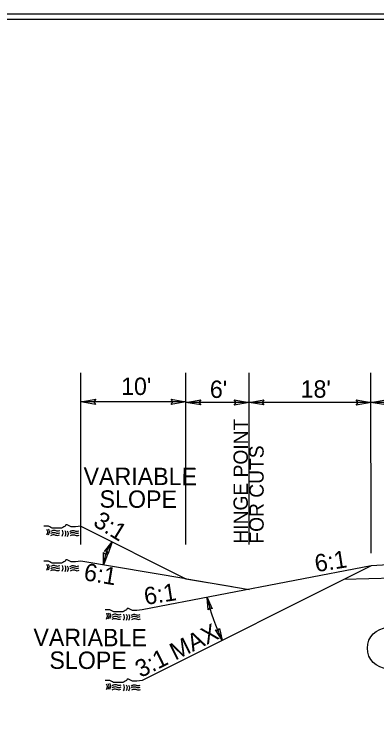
# Model space of a CAD drawing. Extents: x 2241081 to 2251104, y 658534 to 663427.
# Drawn here: x 2247921.2 to 2248093.7, y 660369.2 to 660704.3 of the extents above; entities that cross this region are included whole.
import ezdxf

# ---------------------------------------------------------------- set-up
doc = ezdxf.new("R2010")
doc.units = 0
for name, color, linetype in [('Old_Level_1', 7, 'Continuous'), ('Old_Level_2', 7, 'Continuous'), ('Prop Dimension', 7, 'Continuous'), ('Prop Dimension Text', 7, 'Continuous'), ('Prop PHM Text', 7, 'Continuous'), ('Sheet Plan CELL', 7, 'Continuous'), ('Sheet Plot Border Inside CELL', 7, 'Continuous'), ('Typical Hinge Slope Interstate CELL', 7, 'Continuous'), ('Typical ID Circle CELL', 7, 'Continuous'), ('Typical Terminator CELL', 7, 'Continuous')]:
    doc.layers.add(name, color=color, linetype=linetype)

msp = doc.modelspace()

# ---------------------------------------------------------------- linework, layer by layer
at = {"layer": 'Old_Level_1'}
for p, q in [((2247952.96, 660461.2), (2248002.96, 660436.2)), ((2248002.96, 660436.2), (2247952.96, 660444.54)), ((2248090.97, 660442.37), (2247982.14, 660421.42)), ((2248002.96, 660436.2), (2248024.96, 660432.54))]:
    msp.add_line(p, q, dxfattribs=at)
for points in [[(2247952.96, 660461.2), (2247950.49, 660460.9), (2247949.88, 660460.9), (2247948.95, 660460.9), (2247948.34, 660460.9), (2247947.72, 660461.2), (2247947.1, 660461.51), (2247946.49, 660461.82), (2247945.87, 660461.82), (2247945.56, 660461.2), (2247944.95, 660460.9), (2247944.33, 660460.59), (2247943.71, 660460.28), (2247943.1, 660460.28), (2247942.48, 660460.28), (2247941.87, 660460.28), (2247941.25, 660460.28), (2247940.63, 660460.28), (2247940.02, 660460.28), (2247939.4, 660460.28), (2247938.78, 660460.59), (2247938.17, 660460.9), (2247937.55, 660461.2), (2247936.63, 660461.2), (2247936.01, 660461.2), (2247935.39, 660461.2)], [(2247952.96, 660444.54), (2247950.49, 660444.23), (2247949.88, 660444.23), (2247948.95, 660444.23), (2247948.34, 660444.23), (2247947.72, 660444.54), (2247947.1, 660444.85), (2247946.49, 660445.16), (2247945.87, 660445.16), (2247945.56, 660444.54), (2247944.95, 660444.23), (2247944.33, 660443.92), (2247943.71, 660443.62), (2247943.1, 660443.62), (2247942.48, 660443.62), (2247941.87, 660443.62), (2247941.25, 660443.62), (2247940.63, 660443.62), (2247940.02, 660443.62), (2247939.4, 660443.62), (2247938.78, 660443.92), (2247938.17, 660444.23), (2247937.55, 660444.54), (2247936.63, 660444.54), (2247936.01, 660444.54), (2247935.39, 660444.54)], [(2247982.14, 660421.42), (2247979.67, 660421.12), (2247979.06, 660421.12), (2247978.13, 660421.12), (2247977.51, 660421.12), (2247976.9, 660421.42), (2247976.28, 660421.73), (2247975.67, 660422.04), (2247975.05, 660422.04), (2247974.74, 660421.42), (2247974.12, 660421.12), (2247973.51, 660420.81), (2247972.89, 660420.5), (2247972.28, 660420.5), (2247971.66, 660420.5), (2247971.04, 660420.5), (2247970.43, 660420.5), (2247969.81, 660420.5), (2247969.2, 660420.5), (2247968.58, 660420.5), (2247967.96, 660420.81), (2247967.35, 660421.12), (2247966.73, 660421.42), (2247965.81, 660421.42), (2247965.19, 660421.42), (2247964.57, 660421.42)], [(2247982.13, 660387.95), (2247979.67, 660387.64), (2247979.05, 660387.64), (2247978.12, 660387.64), (2247977.51, 660387.64), (2247976.89, 660387.95), (2247976.28, 660388.26), (2247975.66, 660388.57), (2247975.04, 660388.57), (2247974.73, 660387.95), (2247974.12, 660387.64), (2247973.5, 660387.33), (2247972.89, 660387.03), (2247972.27, 660387.03), (2247971.65, 660387.03), (2247971.04, 660387.03), (2247970.42, 660387.03), (2247969.81, 660387.03), (2247969.19, 660387.03), (2247968.57, 660387.03), (2247967.96, 660387.33), (2247967.34, 660387.64), (2247966.72, 660387.95), (2247965.8, 660387.95), (2247965.18, 660387.95), (2247964.57, 660387.95)]]:
    msp.add_lwpolyline(points, dxfattribs=at)
for points in [[(2247936.65, 660459.76), (2247937.07, 660458.51), (2247936.61, 660456.87)], [(2247936.65, 660459.76), (2247937.07, 660458.51), (2247936.61, 660456.87)], [(2247937.43, 660459.84), (2247937.85, 660458.6), (2247937.4, 660456.95)], [(2247937.43, 660459.84), (2247937.85, 660458.6), (2247937.4, 660456.95)], [(2247938.75, 660457.83), (2247940.26, 660458.25), (2247941.84, 660457.84), (2247942.98, 660458.1)], [(2247938.75, 660457.83), (2247940.26, 660458.25), (2247941.84, 660457.84), (2247942.98, 660458.1)], [(2247938.76, 660458.87), (2247940.26, 660459.3), (2247941.85, 660458.9), (2247942.99, 660459.16)], [(2247938.76, 660458.87), (2247940.26, 660459.3), (2247941.85, 660458.9), (2247942.99, 660459.16)], [(2247944.02, 660459.23), (2247944.43, 660457.99), (2247943.99, 660456.34)], [(2247944.02, 660459.23), (2247944.43, 660457.99), (2247943.99, 660456.34)], [(2247945.33, 660459.13), (2247945.75, 660457.88), (2247945.3, 660456.23)], [(2247945.33, 660459.13), (2247945.75, 660457.88), (2247945.3, 660456.23)], [(2247946.54, 660459.02), (2247946.96, 660457.77), (2247946.51, 660456.13)], [(2247946.54, 660459.02), (2247946.96, 660457.77), (2247946.51, 660456.13)], [(2247947.78, 660458.73), (2247949.29, 660459.16), (2247950.88, 660458.75), (2247952.03, 660459.01)], [(2247947.78, 660458.73), (2247949.29, 660459.16), (2247950.88, 660458.75), (2247952.03, 660459.01)], [(2247947.82, 660457.79), (2247949.33, 660458.22), (2247950.92, 660457.81), (2247952.06, 660458.07)], [(2247947.82, 660457.79), (2247949.33, 660458.22), (2247950.92, 660457.81), (2247952.06, 660458.07)], [(2247938.63, 660456.77), (2247940.14, 660457.19), (2247941.73, 660456.8), (2247942.88, 660457.05)], [(2247938.63, 660456.77), (2247940.14, 660457.19), (2247941.73, 660456.8), (2247942.88, 660457.05)], [(2247947.98, 660456.69), (2247949.48, 660457.12), (2247951.07, 660456.72), (2247952.22, 660456.98)], [(2247947.98, 660456.69), (2247949.48, 660457.12), (2247951.07, 660456.72), (2247952.22, 660456.98)], [(2247936.65, 660443.09), (2247937.07, 660441.85), (2247936.61, 660440.2)], [(2247936.65, 660443.09), (2247937.07, 660441.85), (2247936.61, 660440.2)], [(2247937.43, 660443.18), (2247937.85, 660441.93), (2247937.4, 660440.29)], [(2247937.43, 660443.18), (2247937.85, 660441.93), (2247937.4, 660440.29)], [(2247938.75, 660441.16), (2247940.26, 660441.59), (2247941.84, 660441.18), (2247942.98, 660441.44)], [(2247938.75, 660441.16), (2247940.26, 660441.59), (2247941.84, 660441.18), (2247942.98, 660441.44)], [(2247938.76, 660442.21), (2247940.26, 660442.64), (2247941.85, 660442.23), (2247942.99, 660442.49)], [(2247938.76, 660442.21), (2247940.26, 660442.64), (2247941.85, 660442.23), (2247942.99, 660442.49)], [(2247944.02, 660442.56), (2247944.43, 660441.32), (2247943.99, 660439.67)], [(2247944.02, 660442.56), (2247944.43, 660441.32), (2247943.99, 660439.67)], [(2247945.33, 660442.46), (2247945.75, 660441.22), (2247945.3, 660439.57)], [(2247945.33, 660442.46), (2247945.75, 660441.22), (2247945.3, 660439.57)], [(2247946.54, 660442.35), (2247946.96, 660441.11), (2247946.51, 660439.46)], [(2247946.54, 660442.35), (2247946.96, 660441.11), (2247946.51, 660439.46)], [(2247947.78, 660442.06), (2247949.29, 660442.49), (2247950.88, 660442.09), (2247952.03, 660442.34)], [(2247947.78, 660442.06), (2247949.29, 660442.49), (2247950.88, 660442.09), (2247952.03, 660442.34)], [(2247947.82, 660441.12), (2247949.33, 660441.55), (2247950.92, 660441.14), (2247952.06, 660441.4)], [(2247947.82, 660441.12), (2247949.33, 660441.55), (2247950.92, 660441.14), (2247952.06, 660441.4)], [(2247938.63, 660440.1), (2247940.14, 660440.53), (2247941.73, 660440.13), (2247942.88, 660440.39)], [(2247938.63, 660440.1), (2247940.14, 660440.53), (2247941.73, 660440.13), (2247942.88, 660440.39)], [(2247947.98, 660440.03), (2247949.48, 660440.46), (2247951.07, 660440.05), (2247952.22, 660440.31)], [(2247947.98, 660440.03), (2247949.48, 660440.46), (2247951.07, 660440.05), (2247952.22, 660440.31)]]:
    msp.add_spline(points, degree=3, dxfattribs=at)
at = {"layer": 'Old_Level_2'}
for p, q in [((2248140.97, 660445.12), (2248090.97, 660442.37)), ((2248300.97, 660440.7), (2248078.08, 660435.93))]:
    msp.add_line(p, q, dxfattribs=at)
for points in [[(2247965.1, 660419.83), (2247965.52, 660418.59), (2247965.06, 660416.95)], [(2247965.1, 660419.83), (2247965.52, 660418.59), (2247965.06, 660416.95)], [(2247965.83, 660419.98), (2247966.25, 660418.73), (2247965.79, 660417.08)], [(2247965.83, 660419.98), (2247966.25, 660418.73), (2247965.79, 660417.08)], [(2247966.61, 660420.06), (2247967.03, 660418.81), (2247966.58, 660417.17)], [(2247966.61, 660420.06), (2247967.03, 660418.81), (2247966.58, 660417.17)], [(2247967.81, 660416.99), (2247969.31, 660417.41), (2247970.91, 660417.02), (2247972.06, 660417.27)], [(2247967.81, 660416.99), (2247969.31, 660417.41), (2247970.91, 660417.02), (2247972.06, 660417.27)], [(2247967.93, 660418.04), (2247969.43, 660418.47), (2247971.02, 660418.06), (2247972.16, 660418.32)], [(2247967.93, 660418.04), (2247969.43, 660418.47), (2247971.02, 660418.06), (2247972.16, 660418.32)], [(2247967.94, 660419.09), (2247969.44, 660419.52), (2247971.03, 660419.12), (2247972.17, 660419.38)], [(2247967.94, 660419.09), (2247969.44, 660419.52), (2247971.03, 660419.12), (2247972.17, 660419.38)], [(2247973.19, 660419.44), (2247973.61, 660418.2), (2247973.17, 660416.56)], [(2247973.19, 660419.44), (2247973.61, 660418.2), (2247973.17, 660416.56)], [(2247974.51, 660419.34), (2247974.93, 660418.1), (2247974.48, 660416.45)], [(2247974.51, 660419.34), (2247974.93, 660418.1), (2247974.48, 660416.45)], [(2247975.72, 660419.23), (2247976.14, 660417.99), (2247975.69, 660416.35)], [(2247975.72, 660419.23), (2247976.14, 660417.99), (2247975.69, 660416.35)], [(2247976.96, 660418.95), (2247978.47, 660419.38), (2247980.05, 660418.97), (2247981.2, 660419.23)], [(2247976.96, 660418.95), (2247978.47, 660419.38), (2247980.05, 660418.97), (2247981.2, 660419.23)], [(2247977, 660418), (2247978.51, 660418.44), (2247980.09, 660418.03), (2247981.24, 660418.29)], [(2247977, 660418), (2247978.51, 660418.44), (2247980.09, 660418.03), (2247981.24, 660418.29)], [(2247977.16, 660416.91), (2247978.66, 660417.34), (2247980.25, 660416.94), (2247981.4, 660417.19)], [(2247965.09, 660386.36), (2247965.51, 660385.12), (2247965.06, 660383.47)], [(2247965.09, 660386.36), (2247965.51, 660385.12), (2247965.06, 660383.47)], [(2247965.82, 660386.5), (2247966.24, 660385.26), (2247965.78, 660383.61)], [(2247965.82, 660386.5), (2247966.24, 660385.26), (2247965.78, 660383.61)], [(2247966.6, 660386.59), (2247967.03, 660385.34), (2247966.57, 660383.7)], [(2247966.6, 660386.59), (2247967.03, 660385.34), (2247966.57, 660383.7)], [(2247967.8, 660383.51), (2247969.31, 660383.94), (2247970.9, 660383.54), (2247972.05, 660383.79)], [(2247967.8, 660383.51), (2247969.31, 660383.94), (2247970.9, 660383.54), (2247972.05, 660383.79)], [(2247967.92, 660384.57), (2247969.43, 660385), (2247971.01, 660384.59), (2247972.16, 660384.85)], [(2247967.92, 660384.57), (2247969.43, 660385), (2247971.01, 660384.59), (2247972.16, 660384.85)], [(2247967.93, 660385.62), (2247969.43, 660386.05), (2247971.02, 660385.64), (2247972.17, 660385.9)], [(2247967.93, 660385.62), (2247969.43, 660386.05), (2247971.02, 660385.64), (2247972.17, 660385.9)], [(2247973.19, 660385.97), (2247973.61, 660384.73), (2247973.16, 660383.08)], [(2247973.19, 660385.97), (2247973.61, 660384.73), (2247973.16, 660383.08)], [(2247974.5, 660385.87), (2247974.92, 660384.63), (2247974.47, 660382.98)], [(2247974.5, 660385.87), (2247974.92, 660384.63), (2247974.47, 660382.98)], [(2247975.71, 660385.76), (2247976.14, 660384.52), (2247975.68, 660382.87)], [(2247975.71, 660385.76), (2247976.14, 660384.52), (2247975.68, 660382.87)], [(2247976.96, 660385.47), (2247978.46, 660385.9), (2247980.05, 660385.5), (2247981.2, 660385.75)], [(2247976.96, 660385.47), (2247978.46, 660385.9), (2247980.05, 660385.5), (2247981.2, 660385.75)], [(2247977, 660384.53), (2247978.5, 660384.96), (2247980.09, 660384.55), (2247981.24, 660384.81)], [(2247977, 660384.53), (2247978.5, 660384.96), (2247980.09, 660384.55), (2247981.24, 660384.81)], [(2247977.15, 660383.44), (2247978.65, 660383.87), (2247980.25, 660383.46), (2247981.39, 660383.72)]]:
    msp.add_spline(points, degree=3, dxfattribs=at)
at = {"layer": 'Prop Dimension'}
for centre, radius, start, end in [((2247982.9, 660441.88), 19.12, 141.6676, 177.4305), ((2248092.46, 660443.79), 81.05, 191.6788, 206.9901)]:
    msp.add_arc(centre, radius, start, end, dxfattribs=at)
at = {"layer": 'Prop Dimension Text'}
for p, q in [((2247952.96, 660452.53), (2247952.96, 660534)), ((2248002.96, 660452.53), (2248002.96, 660534)), ((2248032.96, 660452.53), (2248032.96, 660534)), ((2248090.97, 660448.41), (2248090.92, 660534)), ((2247952.96, 660520.32), (2247952.96, 660520.32)), ((2248002.96, 660520.19), (2247952.96, 660520.19)), ((2248002.96, 660520.32), (2248002.96, 660520.32)), ((2248032.96, 660519.93), (2248002.96, 660519.93)), ((2248090.97, 660519.93), (2248032.96, 660519.93)), ((2248150.93, 660519.97), (2248090.93, 660519.93))]:
    msp.add_line(p, q, dxfattribs=at)
at = {"layer": 'Sheet Plan CELL'}
for points in [[(2247801.99, 659651.78), (2247801.97, 660701.75), (2249101.96, 660701.79), (2249101.97, 660551.73), (2249302.01, 660551.71), (2249302.01, 659651.78)], [(2249302.03, 660701.78), (2247801.99, 660701.78), (2247801.99, 659651.78), (2249302.01, 659651.78)]]:
    msp.add_lwpolyline(points, close=True, dxfattribs=at)
at = {"layer": 'Sheet Plot Border Inside CELL'}
msp.add_lwpolyline([(2247648.51, 659649.27), (2249314.49, 659649.28), (2249314.51, 660704.26), (2247648.51, 660704.27)], close=True, dxfattribs=at)
at = {"layer": 'Typical Hinge Slope Interstate CELL'}
for p, q in [((2248090.97, 660442.37), (2247982.13, 660387.95)), ((2248002.46, 660436.29), (2248032.96, 660431.2))]:
    msp.add_line(p, q, dxfattribs=at)
at = {"layer": 'Typical ID Circle CELL'}
msp.add_circle((2248098.83, 660403.27), 9.62, dxfattribs=at)
at = {"layer": 'Typical Terminator CELL'}
for points in [[(2247959.99, 660518.98), (2247952.96, 660520.19), (2247960.03, 660521.44), (2247959.13, 660520.19)], [(2247995.93, 660521.41), (2248002.96, 660520.19), (2247995.89, 660518.94), (2247996.79, 660520.19)], [(2248009.99, 660518.72), (2248002.96, 660519.93), (2248010.03, 660521.18), (2248009.13, 660519.93)], [(2248025.93, 660521.14), (2248032.96, 660519.93), (2248025.89, 660518.68), (2248026.79, 660519.93)], [(2248039.99, 660518.72), (2248032.96, 660519.93), (2248040.03, 660521.18), (2248039.13, 660519.93)], [(2248083.94, 660521.14), (2248090.97, 660519.93), (2248083.9, 660518.68), (2248084.8, 660519.93)], [(2248097.96, 660518.73), (2248090.93, 660519.93), (2248097.99, 660521.19), (2248097.1, 660519.94)], [(2247964.24, 660449.17), (2247967.9, 660453.73), (2247965.99, 660448.16), (2247965.45, 660449.3)], [(2247965.79, 660448.23), (2247963.8, 660442.73), (2247963.81, 660448.62), (2247964.69, 660447.72)], [(2248013.48, 660421.54), (2248013.08, 660427.38), (2248015.45, 660421.99), (2248014.28, 660422.46)], [(2248018.83, 660412.68), (2248020.23, 660407), (2248016.96, 660411.9), (2248018.2, 660411.64)]]:
    msp.add_lwpolyline(points, close=True, dxfattribs=at)

# ---------------------------------------------------------------- texts
at = {"layer": 'Prop Dimension Text'}
for s, rotation, p in [("10'", 359.9999, (2247972.1, 660523.46)), ("6'", 359.9999, (2248014.32, 660522.06)), ("18'", 359.9999, (2248057.47, 660522.17)), ('6:1', 8.8656, (2248064.82, 660439.33)), ('6:1', 8.8656, (2247983.7, 660423.75))]:
    msp.add_text(s, height=8.25, rotation=rotation, dxfattribs=at).set_placement(p)
at = {"layer": 'Prop PHM Text'}
for s, height, p in [('HINGE POINT', 6.8193, (2248032.39, 660452.91)), ('FOR CUTS', 6.819, (2248039.9, 660452.91))]:
    msp.add_text(s, height=height, rotation=89.9999, dxfattribs=at).set_placement(p)
at = {"layer": 'Typical Hinge Slope Interstate CELL'}
for s, rotation, p in [('VARIABLE', 359.8157, (2247954.26, 660480.8)), ('SLOPE', 359.8157, (2247961.87, 660469.96)), ('3:1', 328.4414, (2247958.34, 660461.73)), ('6:1', 350.5376, (2247954.01, 660435.6)), ('3:1 MAX', 26.565, (2247981.42, 660389.06)), ('VARIABLE', 359.8157, (2247930.4, 660404.31)), ('SLOPE', 359.8157, (2247938.02, 660393.47))]:
    msp.add_text(s, height=8.25, rotation=rotation, dxfattribs=at).set_placement(p)

doc.saveas('drawing.dxf')
